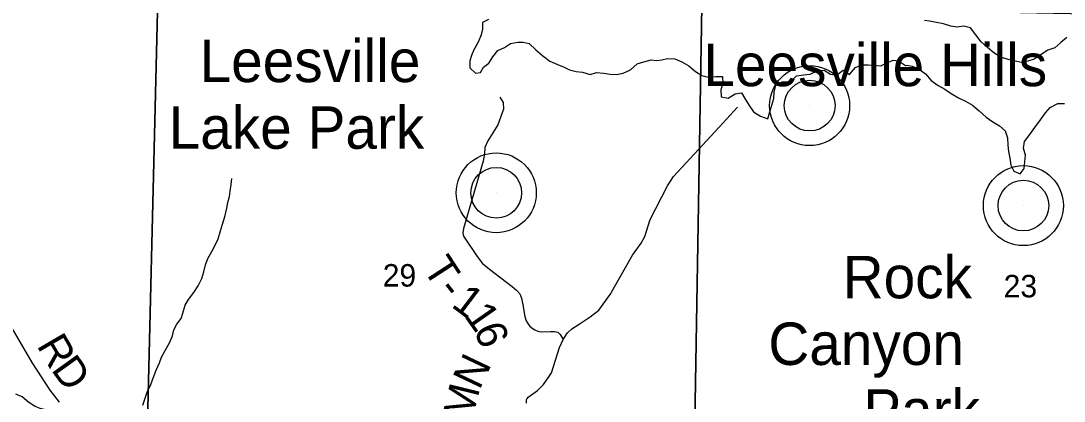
# Model space of a CAD drawing. Extents: x -7.1 to 34, y 0 to 22.
# Drawn here: x 4.468 to 6.409, y 19.056 to 19.764 of the extents above; entities that cross this region are included whole.
import ezdxf

# ---------------------------------------------------------------- set-up
doc = ezdxf.new("R2010")
doc.units = 0
for name, color, linetype in [('GM_X_County_Road', 7, 'Continuous'), ('GM_X_County_Road_Text', 7, 'Continuous'), ('GM_X_Major_Lake', 7, 'Continuous'), ('GM_X_Major_River', 7, 'Continuous'), ('GM_X_Minor_River', 7, 'Continuous'), ('GM_X_Section', 7, 'Continuous'), ('GM_X_Section_Text', 7, 'Continuous'), ('GM_X_Township_Road', 7, 'Continuous'), ('GM_X_Township_Road_Text', 7, 'Continuous'), ('GM_X_Unincorporated', 7, 'Continuous'), ('GM_X_Unincorporated_Location', 7, 'Continuous'), ('GM_X_Unincorporated_Text', 7, 'Continuous')]:
    doc.layers.add(name, color=color, linetype=linetype)

msp = doc.modelspace()

# ---------------------------------------------------------------- linework, layer by layer
at = {"layer": 'GM_X_County_Road'}
msp.add_line((5.7672, 19.566), (5.8015, 19.6031), dxfattribs=at)
msp.add_lwpolyline([(5.4084, 19.052), (5.4087, 19.058), (5.4092, 19.0601), (5.4104, 19.0617), (5.4117, 19.063), (5.429, 19.0759), (5.4402, 19.0871), (5.4501, 19.1009), (5.4551, 19.1086), (5.4703, 19.156), (5.4771, 19.1705), (5.4851, 19.1832), (5.4931, 19.1905), (5.5069, 19.1991), (5.5269, 19.2128), (5.5431, 19.2252), (5.5642, 19.2544), (5.606, 19.3279), (5.622, 19.3502), (5.6286, 19.3621), (5.6387, 19.3938), (5.6708, 19.4564), (5.6823, 19.474), (5.7672, 19.566)], dxfattribs=at)
at = {"layer": 'GM_X_Major_Lake'}
for points in [[(5.3377, 19.7661), (5.3267, 19.761), (5.3269, 19.7481), (5.3241, 19.7378), (5.3186, 19.7241), (5.3108, 19.7099), (5.3061, 19.6996), (5.3032, 19.6897), (5.3034, 19.6764), (5.3138, 19.6667), (5.3233, 19.668), (5.3285, 19.6776), (5.3386, 19.6853), (5.3457, 19.6968), (5.3554, 19.7084), (5.3674, 19.7142), (5.3791, 19.7216), (5.3927, 19.7242), (5.4022, 19.7243), (5.4137, 19.7215), (5.4257, 19.7099), (5.4391, 19.6987), (5.4522, 19.6891), (5.4653, 19.6832), (5.479, 19.6778), (5.4886, 19.6726), (5.5008, 19.6698), (5.513, 19.6681), (5.5268, 19.6641), (5.5389, 19.6674), (5.5518, 19.6665), (5.5644, 19.6648), (5.5762, 19.6642), (5.5883, 19.6667), (5.6023, 19.6726), (5.6146, 19.6838), (5.6271, 19.6878), (5.6404, 19.6911), (5.651, 19.6901), (5.6605, 19.691), (5.6707, 19.6935), (5.6844, 19.6929), (5.6974, 19.6878), (5.7109, 19.6801), (5.7232, 19.6697), (5.7351, 19.6619), (5.7473, 19.6591), (5.761, 19.6601), (5.7732, 19.6603), (5.7738, 19.6481), (5.7702, 19.6352), (5.7711, 19.6223), (5.7841, 19.6202), (5.7969, 19.628), (5.8087, 19.6301), (5.8149, 19.6196), (5.8227, 19.6061), (5.8313, 19.5945), (5.8443, 19.5867), (5.8574, 19.5812), (5.8613, 19.5942), (5.8653, 19.6068), (5.8689, 19.619), (5.8695, 19.6311), (5.8727, 19.6441), (5.8843, 19.6503), (5.8999, 19.6506), (5.9111, 19.6618), (5.9241, 19.6632), (5.9366, 19.6645), (5.9509, 19.6716), (5.9623, 19.6721), (5.9746, 19.6647), (5.9856, 19.6627), (5.998, 19.672), (6.0096, 19.6642), (6.0208, 19.6773), (6.0321, 19.682), (6.0446, 19.6822), (6.0549, 19.6813), (6.0678, 19.68), (6.0792, 19.6855), (6.0912, 19.6906), (6.1008, 19.6896), (6.1138, 19.6807)], [(6.414, 19.7328), (6.4032, 19.7235), (6.3919, 19.7134), (6.3787, 19.709), (6.3663, 19.7013), (6.3535, 19.6927), (6.3414, 19.6887), (6.3297, 19.6862), (6.3178, 19.6887), (6.3049, 19.6919), (6.2911, 19.6962), (6.2784, 19.7043), (6.2665, 19.7144), (6.2549, 19.7248), (6.2448, 19.7379), (6.2347, 19.7507), (6.2225, 19.7542), (6.2096, 19.7521), (6.1981, 19.7542), (6.1844, 19.7582), (6.1714, 19.761), (6.1588, 19.7634), (6.1493, 19.7644)], [(6.1138, 19.6807), (6.1161, 19.6811), (6.1264, 19.6798), (6.139, 19.6739), (6.151, 19.665), (6.1618, 19.6527), (6.1745, 19.6438), (6.1868, 19.6364), (6.1991, 19.6287), (6.2122, 19.6205), (6.2256, 19.6143), (6.2386, 19.6066), (6.251, 19.5961), (6.2641, 19.5846), (6.2764, 19.5757), (6.2887, 19.5687), (6.2995, 19.559), (6.3035, 19.5458), (6.3045, 19.5325), (6.3058, 19.5204), (6.3083, 19.5083), (6.3097, 19.4951), (6.3152, 19.4838), (6.3274, 19.479), (6.3349, 19.4887), (6.3362, 19.5012), (6.3371, 19.5141), (6.3335, 19.5269), (6.3352, 19.5395), (6.3452, 19.5522), (6.3545, 19.5652), (6.3649, 19.5794), (6.3742, 19.5925), (6.3831, 19.6025), (6.3971, 19.61), (6.41, 19.6098)]]:
    msp.add_lwpolyline(points, dxfattribs=at)
at = {"layer": 'GM_X_Major_River'}
msp.add_lwpolyline([(4.5776, 18.929), (4.5774, 18.9416), (4.573, 18.9514), (4.5679, 18.9627), (4.5643, 18.9725), (4.5592, 18.9853), (4.5563, 18.9981), (4.5561, 19.011), (4.5521, 19.0231), (4.5398, 19.0309), (4.5295, 19.0349), (4.5165, 19.0392), (4.5039, 19.0421), (4.4943, 19.0457), (4.4824, 19.0531), (4.4701, 19.0639), (4.4582, 19.069)], dxfattribs=at)
at = {"layer": 'GM_X_Minor_River'}
msp.add_lwpolyline([(4.6945, 19.0486), (4.6993, 19.0611), (4.703, 19.0726), (4.7097, 19.0866), (4.7145, 19.1004), (4.7197, 19.1133), (4.7257, 19.1274), (4.7294, 19.1377), (4.7365, 19.1499), (4.7443, 19.1647), (4.7499, 19.1773), (4.7525, 19.1887), (4.7577, 19.199), (4.766, 19.2097), (4.7693, 19.2196), (4.7734, 19.2344), (4.7797, 19.2451), (4.7899, 19.2581), (4.7974, 19.2707), (4.8045, 19.284), (4.8082, 19.2966), (4.8115, 19.3099), (4.8159, 19.3217), (4.823, 19.3347), (4.8298, 19.3472), (4.8346, 19.3579), (4.839, 19.3731), (4.8427, 19.3853), (4.8479, 19.4013), (4.8508, 19.415), (4.853, 19.4256), (4.8559, 19.437), (4.8574, 19.4469), (4.8588, 19.4594), (4.8606, 19.4704)], dxfattribs=at)
at = {"layer": 'GM_X_Section'}
for points in [[(3.8731, 19.8315), (4.7229, 19.8074), (4.6987, 18.8125), (3.8597, 18.828), (3.8749, 19.7341)], [(4.7229, 19.8074), (5.7351, 19.7911), (5.7181, 18.7951), (4.6987, 18.8125)], [(6.7637, 19.7708), (6.7487, 18.7741), (5.7181, 18.7951), (5.7351, 19.7911)]]:
    msp.add_lwpolyline(points, close=True, dxfattribs=at)
at = {"layer": 'GM_X_Township_Road'}
for points in [[(5.3588, 19.6215), (5.3651, 19.6117), (5.3661, 19.5992), (5.3552, 19.5702), (5.3366, 19.5406), (5.3308, 19.5279), (5.3306, 19.5161), (5.3278, 19.5028), (5.2911, 19.3771), (5.2901, 19.3695), (5.2917, 19.3631), (5.317, 19.3253), (5.3268, 19.3118), (5.3399, 19.3016), (5.382, 19.2693), (5.3905, 19.262), (5.3963, 19.2555), (5.3991, 19.2473), (5.402, 19.2354), (5.4054, 19.2137), (5.4082, 19.2056), (5.4108, 19.2006), (5.4141, 19.1963), (5.4191, 19.1919), (5.4242, 19.1888), (5.4295, 19.1863), (5.4362, 19.1848), (5.4531, 19.1856), (5.4606, 19.1857), (5.4668, 19.184), (5.4715, 19.1801), (5.4771, 19.1705)], [(4.4465, 19.1989), (4.488, 19.1277), (4.5214, 19.0765), (4.539, 19.0537)]]:
    msp.add_lwpolyline(points, dxfattribs=at)
at = {"layer": 'GM_X_Unincorporated'}
for centre, radius in [((5.9355, 19.606), 0.0744), ((5.9355, 19.606), 0.0472), ((5.3523, 19.4437), 0.0744), ((5.3523, 19.4437), 0.0472), ((6.3332, 19.4199), 0.0744), ((6.3332, 19.4199), 0.0472)]:
    msp.add_circle(centre, radius, dxfattribs=at)
at = {"layer": 'GM_X_Unincorporated_Location'}
for p, q in [((5.9355, 19.606), (5.9355, 19.606)), ((5.3523, 19.4437), (5.3523, 19.4437)), ((6.3332, 19.4199), (6.3332, 19.4199))]:
    msp.add_line(p, q, dxfattribs=at)

# ---------------------------------------------------------------- texts
at = {"layer": 'GM_X_County_Road_Text'}
for s, rotation, p in [('N', 64.6063, (5.321, 19.0753)), ('M', 76.2281, (5.3074, 19.0182))]:
    msp.add_text(s, height=0.0568, rotation=rotation, dxfattribs=at).set_placement(p)
at = {"layer": 'GM_X_Section_Text'}
for s, p in [('29', (5.1411, 19.2691)), ('23', (6.2965, 19.2491))]:
    msp.add_text(s, height=0.04186, rotation=0, dxfattribs=at).set_placement(p)
at = {"layer": 'GM_X_Township_Road_Text'}
for s, rotation, p in [('T', 302.9674, (5.2147, 19.3025)), ('-', 308.0466, (5.241, 19.2624)), ('1', 322.8642, (5.2668, 19.2328)), ('1', 305.0383, (5.2915, 19.215)), ('6', 291.6333, (5.3099, 19.1895)), ('R', 300.3205, (4.4963, 19.1595)), ('D', 305.6153, (4.5229, 19.1145))]:
    msp.add_text(s, height=0.0568, rotation=rotation, dxfattribs=at).set_placement(p)
at = {"layer": 'GM_X_Unincorporated_Text'}
for s, height, p in [('Leesville', 0.07898, (4.8003, 19.6498)), ('Leesville Hills', 0.078977, (5.7378, 19.6423)), ('Lake Park', 0.07898, (4.7428, 19.5257)), ('Rock', 0.07898, (5.9969, 19.2473)), ('Canyon', 0.07898, (5.8586, 19.1232)), ('Park', 0.07898, (6.0353, 18.999))]:
    msp.add_text(s, height=height, rotation=0, dxfattribs=at).set_placement(p)

doc.saveas('drawing.dxf')
